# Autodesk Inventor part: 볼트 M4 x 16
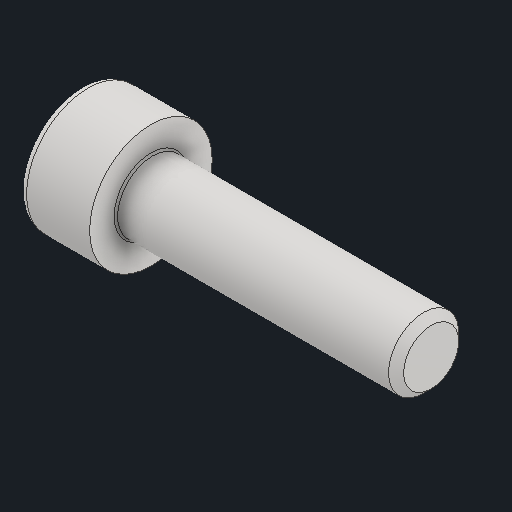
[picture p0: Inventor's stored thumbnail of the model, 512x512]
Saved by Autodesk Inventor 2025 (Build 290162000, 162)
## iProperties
Created: 2025-08
Part Number: 볼트 M4 x 16
Material: 스테인리스강
Description: 6각 소켓 머리 캡 나사
Document SubType Name: Modeling
Designer: infra002
Density: 8.08 g/cm^3
Appearance: 기본값
Author: jhkim
Sending System: Autodesk Inventor 2026
Preprocessor: ST-DEVELOPER v20.1
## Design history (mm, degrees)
feature "Solid1"
node "솔리드1"
